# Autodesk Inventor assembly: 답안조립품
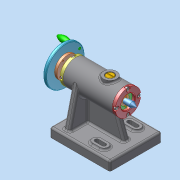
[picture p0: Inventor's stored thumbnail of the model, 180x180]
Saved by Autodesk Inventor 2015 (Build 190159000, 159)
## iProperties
Created: 2026-09
Part Number: 답안조립품
Document SubType Name: Assembly
Designer: SCD-A06
Author: SCD-A06
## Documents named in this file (18)
- C:\Users\SCD-A06\Desktop\760903V1012\답안조립품.iam
- C:\Users\SCD-A06\Desktop\760903V1012\답안조립품.ipt
- C:\Users\SCD-A06\Desktop\760903V1012\6각 구멍붙이 볼트 M3x8.ipt
- C:\Users\SCD-A06\Desktop\760903V1012\6각 너트 M8.ipt
- C:\Users\SCD-A06\Desktop\760903V1012\가이드 부시.ipt
- C:\Users\SCD-A06\Desktop\760903V1012\나사축.ipt
- C:\Users\SCD-A06\Desktop\760903V1012\돌림판.ipt
- C:\Users\SCD-A06\Desktop\760903V1012\멈춤나사 M3.ipt
- C:\Users\SCD-A06\Desktop\760903V1012\부시.ipt
- C:\Users\SCD-A06\Desktop\760903V1012\센터.ipt
- C:\Users\SCD-A06\Desktop\760903V1012\센터홀더.ipt
- C:\Users\SCD-A06\Desktop\760903V1012\스톱퍼.ipt
- C:\Users\SCD-A06\Desktop\760903V1012\슬리브.ipt
- C:\Users\SCD-A06\Desktop\760903V1012\커버.ipt
- C:\Users\SCD-A06\Desktop\760903V1012\평 와셔 M8.ipt
- C:\Users\SCD-A06\Desktop\760903V1012\평행 키 4x4x10.ipt
- C:\Users\SCD-A06\Desktop\760903V1012\플랜지.ipt
- C:\Users\SCD-A06\Desktop\760903V1012\핸들.ipt
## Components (16 placed, 5 different names)
1. 6각 구멍붙이 볼트 M3x8:1
2. 6각 너트 M8:1
3. 가이드 부시:1
4. 플랜지:1
5. 핸들:1
6. 6각 구멍붙이 볼트 M3x8:2
7. 6각 구멍붙이 볼트 M3x8:3
8. 6각 구멍붙이 볼트 M3x8:4
9. 6각 구멍붙이 볼트 M3x8:5
10. 6각 구멍붙이 볼트 M3x8:6
11. 6각 구멍붙이 볼트 M3x8:7
12. 6각 구멍붙이 볼트 M3x8:8
13. 6각 구멍붙이 볼트 M3x8:9
14. 6각 구멍붙이 볼트 M3x8:10
15. 6각 구멍붙이 볼트 M3x8:11
16. 6각 구멍붙이 볼트 M3x8:12
